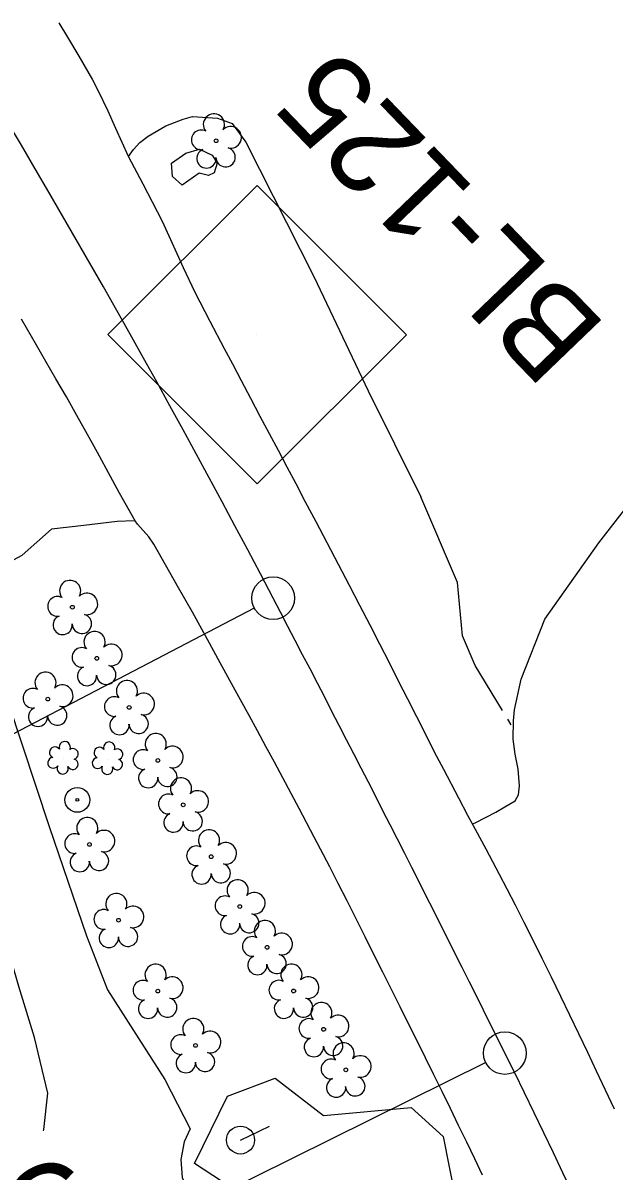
# Model space of a CAD drawing. Extents: x 471894 to 476235, y 503501 to 507878.
# Drawn here: x 474257.8 to 474361.6, y 505265.7 to 505467.5 of the extents above; entities that cross this region are included whole.
import ezdxf

# ---------------------------------------------------------------- set-up
doc = ezdxf.new("R2010")
doc.units = 0
for name, color, linetype in [('CTL Secondary Horizontal and Vertical CELL', 7, 'Continuous'), ('CTL Secondary Horizontal and Vertical Text', 7, 'Continuous'), ('Exist Horizontal Alignment', 7, 'Continuous'), ('Exist Other Culture Area Outline', 7, 'Continuous'), ('Exist Roads EOP', 7, 'Continuous'), ('Exist Roads EOP Other', 7, 'Continuous'), ('Exist Roads Soil', 7, 'Continuous'), ('Exist Utilities Other Located Object CELL', 7, 'Continuous'), ('Exist Utilities Power Pole CELL', 7, 'Continuous'), ('Exist Vegetation Hedge Row', 7, 'Continuous'), ('Exist Vegetation Shrub CELL', 7, 'Continuous'), ('Exist Vegetation Tree CELL', 7, 'Continuous')]:
    doc.layers.add(name, color=color, linetype=linetype)

msp = doc.modelspace()

# ---------------------------------------------------------------- linework, layer by layer
at = {"layer": 'CTL Secondary Horizontal and Vertical CELL'}
msp.add_line((474298.76, 505412.66), (474298.76, 505412.66), dxfattribs=at)
msp.add_lwpolyline([(474272.68, 505412.74), (474298.89, 505438.95), (474325.14, 505412.7), (474298.93, 505386.49)], close=True, dxfattribs=at)
at = {"layer": 'Exist Horizontal Alignment'}
for p, q in [((474298.4, 505364.65), (474150.86, 505287.54)), ((474339.07, 505284.76), (474231.53, 505231.46))]:
    msp.add_line(p, q, dxfattribs=at)
for centre in [(474301.73, 505366.39), (474342.43, 505286.42)]:
    msp.add_circle(centre, 3.75, dxfattribs=at)
for centre, radius, start, end in [((472721.75, 504540.63), 1782.75, 27.59346, 37.45515), ((470598.26, 503430.81), 4178.77, 26.36313, 27.59346), ((473181.76, 504711.19), 1295.4, 20.84556, 26.36313)]:
    msp.add_arc(centre, radius, start, end, dxfattribs=at)
at = {"layer": 'Exist Other Culture Area Outline'}
msp.add_lwpolyline([(474285.71, 505439), (474284.06, 505440.54), (474283.88, 505442.89), (474286.39, 505444.64), (474288.8, 505445.35), (474290.98, 505444.29), (474291.87, 505442.87), (474291.38, 505441.19), (474290.36, 505440.7), (474288.72, 505441.12), (474285.71, 505439)], dxfattribs=at)
at = {"layer": 'Exist Roads EOP'}
for points in [[(474264.05, 505467.56), (474265.59, 505465.04), (474267.6, 505461.65), (474269.95, 505457.52), (474271, 505455.56), (474272.68, 505452.05), (474274, 505449.04), (474276.22, 505444.1), (474278.82, 505439.21), (474280.49, 505436.05), (474282.19, 505432.67), (474283.69, 505429.45), (474285.89, 505424.51), (474287.94, 505420.2), (474290.58, 505415.09), (474293.12, 505410.28), (474294.56, 505407.56), (474296.1, 505404.65), (474297.74, 505401.55), (474299.4, 505398.4), (474301.02, 505395.34), (474302.59, 505392.38), (474304.11, 505389.5), (474305.68, 505386.54), (474307.37, 505383.33), (474309.2, 505379.87), (474311.16, 505376.15), (474313.15, 505372.36), (474315.07, 505368.69), (474316.92, 505365.14), (474318.69, 505361.71), (474320.4, 505358.37), (474322.08, 505355.09), (474323.71, 505351.86), (474325.31, 505348.69), (474326.88, 505345.57), (474328.46, 505342.46), (474330.04, 505339.38), (474331.63, 505336.32), (474334.28, 505331.26), (474335.88, 505328.26), (474337.23, 505325.79), (474339.1, 505322.33), (474341.46, 505317.88), (474342.8, 505315.29), (474344.26, 505312.45), (474345.79, 505309.44), (474347.35, 505306.33), (474348.94, 505303.11), (474350.56, 505299.8), (474352.19, 505296.45), (474353.8, 505293.13), (474355.38, 505289.84), (474356.94, 505286.57), (474358.5, 505283.3), (474360.06, 505279.98), (474361.63, 505276.6)], [(474338.5, 505264.94), (474337.13, 505267.84), (474335.73, 505270.75), (474334.31, 505273.7), (474332.87, 505276.66), (474331.41, 505279.64), (474329.94, 505282.62), (474328.47, 505285.59), (474327, 505288.55), (474325.52, 505291.53), (474324.02, 505294.54), (474322.5, 505297.58), (474320.97, 505300.65), (474319.43, 505303.74), (474317.87, 505306.86), (474316.3, 505310), (474314.71, 505313.16), (474313.15, 505316.24), (474311.67, 505319.13), (474308.95, 505324.36), (474306.29, 505329.4), (474304.88, 505332.05), (474303.43, 505334.8), (474301.94, 505337.58), (474300.46, 505340.34), (474298.97, 505343.07), (474297.49, 505345.77), (474294.74, 505350.77), (474292.43, 505355), (474290.17, 505359.15), (474287.52, 505363.91), (474285.11, 505368.18), (474283.57, 505370.89), (474280.77, 505375.91), (474279.88, 505377.18), (474277.9, 505379.38), (474277.45, 505379.96), (474274.73, 505384.87), (474272.39, 505389.19), (474270.86, 505391.97), (474269.09, 505395.15), (474267.22, 505398.5), (474265.38, 505401.76), (474263.56, 505404.93), (474261.78, 505408.02), (474260.13, 505410.87), (474257.52, 505415.42)]]:
    msp.add_lwpolyline(points, dxfattribs=at)
at = {"layer": 'Exist Roads EOP Other'}
for points in [[(474344.12, 505346.75), (474345.27, 505352.15), (474349.48, 505362.68), (474358.95, 505376.1), (474368.94, 505389), (474377.53, 505395.2)], [(474255.2, 505347.88), (474252.68, 505357.39), (474252.15, 505364.02), (474252.53, 505366.97), (474253.79, 505370.24), (474254.59, 505372.28), (474257.6, 505373.92), (474262.76, 505378.5)], [(474277.31, 505379.96), (474274.34, 505379.89), (474268.47, 505379.19), (474262.76, 505378.5)], [(474255.2, 505347.88), (474262.34, 505326.27), (474268.91, 505307.01), (474272.6, 505297.55), (474282.7, 505281.77), (474287.12, 505273.12), (474286.07, 505270.82), (474285.47, 505267.68), (474285.75, 505264.57), (474287.25, 505261.46), (474289.99, 505259.33), (474310.71, 505247.24), (474328.8, 505234.96), (474323.9, 505226.78), (474305.98, 505237.39), (474292.34, 505242.83), (474281.37, 505243.82)], [(474336.82, 505326.74), (474337.33, 505326.94), (474340.84, 505328.76), (474342.45, 505329.69), (474344.25, 505330.76), (474344.82, 505331.82), (474345.01, 505333.38), (474344.76, 505336.35), (474344.27, 505338.99), (474343.91, 505341.58), (474343.97, 505344.84), (474344.12, 505346.75)], [(474343.56, 505344.11), (474342.94, 505345.13)], [(474261.34, 505272.77), (474261.44, 505272.96), (474262.1, 505279.36), (474259.8, 505289.16), (474257.04, 505298.11), (474253.18, 505311.36), (474249.07, 505328.08), (474244.58, 505342.07)]]:
    msp.add_lwpolyline(points, dxfattribs=at)
at = {"layer": 'Exist Roads Soil'}
for points in [[(474276.29, 505444.04), (474277.2, 505445.27), (474278.28, 505446.48), (474279.74, 505447.62), (474282.84, 505449.45), (474285.91, 505450.59), (474287.54, 505451.05)], [(474287.54, 505451.05), (474291.96, 505450.78), (474294.54, 505449.81), (474296.93, 505446.54), (474308.86, 505422.93), (474318.39, 505402.82), (474327.68, 505384.22)], [(474342.03, 505346.62), (474337.19, 505354.56), (474335.01, 505359.76), (474334.09, 505369.12), (474327.68, 505384.22)]]:
    msp.add_lwpolyline(points, dxfattribs=at)
at = {"layer": 'Exist Utilities Other Located Object CELL'}
for radius in [2.18, 0.24]:
    msp.add_circle((474267.31, 505330.93), radius, dxfattribs=at)
at = {"layer": 'Exist Utilities Power Pole CELL'}
for q in [(474301.06, 505273.54), (474295.98, 505271.12)]:
    msp.add_line((474295.98, 505271.12), q, dxfattribs=at)
msp.add_circle((474295.98, 505271.12), 2.45, dxfattribs=at)
at = {"layer": 'Exist Vegetation Hedge Row'}
msp.add_lwpolyline([(474311.95, 505251.22), (474287.89, 505267.03), (474293.69, 505278.83), (474302.08, 505282.03), (474310.58, 505275.45), (474325.97, 505276.84), (474331.58, 505271.74), (474333.63, 505261.37)], dxfattribs=at)
at = {"layer": 'Exist Vegetation Shrub CELL'}
for p, q in [((474264.87, 505338.14), (474264.87, 505338.14)), ((474272.69, 505338.08), (474272.69, 505338.08))]:
    msp.add_line(p, q, dxfattribs=at)
for centre, radius, start, end in [((474263.39, 505339.27), 0.968, 35.8908, 245.4216), ((474265.1, 505340.18), 0.99, 334.8391, 200.4717), ((474271.21, 505339.21), 0.968, 35.8908, 245.4216), ((474272.92, 505340.12), 0.99, 334.8391, 200.4717), ((474263.07, 505337.44), 0.955, 95.1099, 327.9534), ((474266.51, 505337.21), 0.937, 204.9913, 73.4601), ((474266.54, 505339.01), 0.929, 284.4567, 126.0861), ((474270.89, 505337.38), 0.955, 95.1099, 327.9534), ((474274.33, 505337.15), 0.937, 204.9913, 73.4601), ((474274.36, 505338.95), 0.929, 284.4567, 126.0861), ((474264.74, 505336.46), 0.984, 151.2797, 21.387), ((474272.56, 505336.4), 0.984, 151.2797, 21.387)]:
    msp.add_arc(centre, radius, start, end, dxfattribs=at)
at = {"layer": 'Exist Vegetation Tree CELL'}
for p, q in [((474291.69, 505446.8), (474291.69, 505446.8)), ((474266.44, 505364.79), (474266.44, 505364.79)), ((474270.73, 505355.81), (474270.73, 505355.81)), ((474262.11, 505348.65), (474262.11, 505348.65)), ((474276.42, 505347.19), (474276.42, 505347.19)), ((474281.47, 505337.86), (474281.47, 505337.86)), ((474285.92, 505330.06), (474285.92, 505330.06)), ((474269.44, 505323.1), (474269.44, 505323.1)), ((474290.84, 505320.94), (474290.84, 505320.94)), ((474295.86, 505312.17), (474295.86, 505312.17)), ((474274.55, 505309.77), (474274.55, 505309.77)), ((474300.66, 505305.01), (474300.66, 505305.01)), ((474281.44, 505297.32), (474281.44, 505297.32)), ((474305.32, 505297.33), (474305.32, 505297.33)), ((474310.59, 505290.59), (474310.59, 505290.59)), ((474288.08, 505287.76), (474288.08, 505287.76)), ((474314.48, 505283.47), (474314.48, 505283.47))]:
    msp.add_line(p, q, dxfattribs=at)
for centre in [(474291.69, 505446.8), (474266.44, 505364.79), (474270.73, 505355.81), (474262.11, 505348.65), (474276.42, 505347.19), (474281.47, 505337.86), (474285.92, 505330.06), (474269.44, 505323.1), (474290.84, 505320.94), (474295.86, 505312.17), (474274.55, 505309.77), (474300.66, 505305.01), (474281.44, 505297.32), (474305.32, 505297.33), (474310.59, 505290.59), (474288.08, 505287.76), (474314.48, 505283.47)]:
    msp.add_circle(centre, 0.326, dxfattribs=at)
for centre, radius, start, end in [((474291.31, 505449.67), 1.86, 330.1651, 219.7134), ((474294.24, 505447.39), 1.9, 257.1011, 134.1999), ((474289.09, 505446.95), 1.73, 62.6636, 279.3457), ((474289.99, 505443.68), 1.69, 111.5671, 6.231), ((474293.37, 505443.9), 1.7, 181.2822, 74.56), ((474266.05, 505367.67), 1.86, 330.1651, 219.7134), ((474263.83, 505364.95), 1.73, 62.6636, 279.3457), ((474268.99, 505365.38), 1.9, 257.1011, 134.1999), ((474264.73, 505361.67), 1.69, 111.5671, 6.231), ((474268.11, 505361.89), 1.7, 181.2822, 74.56), ((474270.34, 505358.69), 1.86, 330.1651, 219.7134), ((474273.28, 505356.4), 1.9, 257.1011, 134.1999), ((474268.12, 505355.97), 1.73, 62.6636, 279.3457), ((474269.02, 505352.69), 1.69, 111.5671, 6.231), ((474272.4, 505352.91), 1.7, 181.2822, 74.56), ((474261.72, 505351.52), 1.86, 330.1651, 219.7134), ((474259.5, 505348.8), 1.73, 62.6636, 279.3457), ((474264.66, 505349.24), 1.9, 257.1011, 134.1999), ((474276.03, 505350.06), 1.86, 330.1651, 219.7134), ((474273.81, 505347.34), 1.73, 62.6636, 279.3457), ((474278.96, 505347.78), 1.9, 257.1011, 134.1999), ((474260.4, 505345.53), 1.69, 111.5671, 6.231), ((474263.78, 505345.75), 1.7, 181.2822, 74.56), ((474274.71, 505344.07), 1.69, 111.5671, 6.231), ((474278.09, 505344.29), 1.7, 181.2822, 74.56), ((474281.09, 505340.73), 1.86, 330.1651, 219.7134), ((474284.02, 505338.45), 1.9, 257.1011, 134.1999), ((474278.86, 505338.02), 1.73, 62.6636, 279.3457), ((474279.77, 505334.74), 1.69, 111.5671, 6.231), ((474283.14, 505334.96), 1.7, 181.2822, 74.56), ((474285.53, 505332.93), 1.86, 330.1651, 219.7134), ((474283.31, 505330.21), 1.73, 62.6636, 279.3457), ((474288.47, 505330.65), 1.9, 257.1011, 134.1999), ((474284.21, 505326.94), 1.69, 111.5671, 6.231), ((474287.59, 505327.16), 1.7, 181.2822, 74.56), ((474269.06, 505325.97), 1.86, 330.1651, 219.7134), ((474266.84, 505323.25), 1.73, 62.6636, 279.3457), ((474271.99, 505323.68), 1.9, 257.1011, 134.1999), ((474290.46, 505323.82), 1.86, 330.1651, 219.7134), ((474271.12, 505320.2), 1.7, 181.2822, 74.56), ((474288.24, 505321.1), 1.73, 62.6636, 279.3457), ((474293.39, 505321.53), 1.9, 257.1011, 134.1999), ((474267.74, 505319.98), 1.69, 111.5671, 6.231), ((474289.14, 505317.82), 1.69, 111.5671, 6.231), ((474292.52, 505318.04), 1.7, 181.2822, 74.56), ((474295.48, 505315.04), 1.86, 330.1651, 219.7134), ((474274.17, 505312.64), 1.86, 330.1651, 219.7134), ((474293.26, 505312.32), 1.73, 62.6636, 279.3457), ((474298.41, 505312.76), 1.9, 257.1011, 134.1999), ((474277.1, 505310.35), 1.9, 257.1011, 134.1999), ((474271.95, 505309.92), 1.73, 62.6636, 279.3457), ((474294.16, 505309.05), 1.69, 111.5671, 6.231), ((474297.53, 505309.27), 1.7, 181.2822, 74.56), ((474300.27, 505307.88), 1.86, 330.1651, 219.7134), ((474272.85, 505306.65), 1.69, 111.5671, 6.231), ((474276.23, 505306.87), 1.7, 181.2822, 74.56), ((474298.05, 505305.16), 1.73, 62.6636, 279.3457), ((474303.2, 505305.59), 1.9, 257.1011, 134.1999), ((474302.33, 505302.11), 1.7, 181.2822, 74.56), ((474281.06, 505300.19), 1.86, 330.1651, 219.7134), ((474298.95, 505301.88), 1.69, 111.5671, 6.231), ((474304.93, 505300.2), 1.86, 330.1651, 219.7134), ((474283.99, 505297.91), 1.9, 257.1011, 134.1999), ((474307.87, 505297.92), 1.9, 257.1011, 134.1999), ((474278.84, 505297.47), 1.73, 62.6636, 279.3457), ((474302.71, 505297.48), 1.73, 62.6636, 279.3457), ((474279.74, 505294.2), 1.69, 111.5671, 6.231), ((474283.11, 505294.42), 1.7, 181.2822, 74.56), ((474303.61, 505294.21), 1.69, 111.5671, 6.231), ((474306.99, 505294.43), 1.7, 181.2822, 74.56), ((474310.2, 505293.46), 1.86, 330.1651, 219.7134), ((474287.69, 505290.64), 1.86, 330.1651, 219.7134), ((474307.98, 505290.74), 1.73, 62.6636, 279.3457), ((474313.14, 505291.17), 1.9, 257.1011, 134.1999), ((474285.47, 505287.92), 1.73, 62.6636, 279.3457), ((474290.63, 505288.35), 1.9, 257.1011, 134.1999), ((474308.88, 505287.46), 1.69, 111.5671, 6.231), ((474312.26, 505287.69), 1.7, 181.2822, 74.56), ((474314.1, 505286.34), 1.86, 330.1651, 219.7134), ((474286.37, 505284.64), 1.69, 111.5671, 6.231), ((474289.75, 505284.86), 1.7, 181.2822, 74.56), ((474317.03, 505284.06), 1.9, 257.1011, 134.1999), ((474311.88, 505283.62), 1.73, 62.6636, 279.3457), ((474312.78, 505280.35), 1.69, 111.5671, 6.231), ((474316.16, 505280.57), 1.7, 181.2822, 74.56)]:
    msp.add_arc(centre, radius, start, end, dxfattribs=at)

# ---------------------------------------------------------------- texts
at = {"layer": 'CTL Secondary Horizontal and Vertical Text'}
msp.add_text('BL-125', height=16, rotation=133.8986, dxfattribs=at).set_placement((474360.58, 505414.04))
at = {"layer": 'Exist Horizontal Alignment'}
msp.add_text('PCC', height=16, rotation=26.3631, dxfattribs=at).set_placement((474232.52, 505234.87))

doc.saveas('drawing.dxf')
